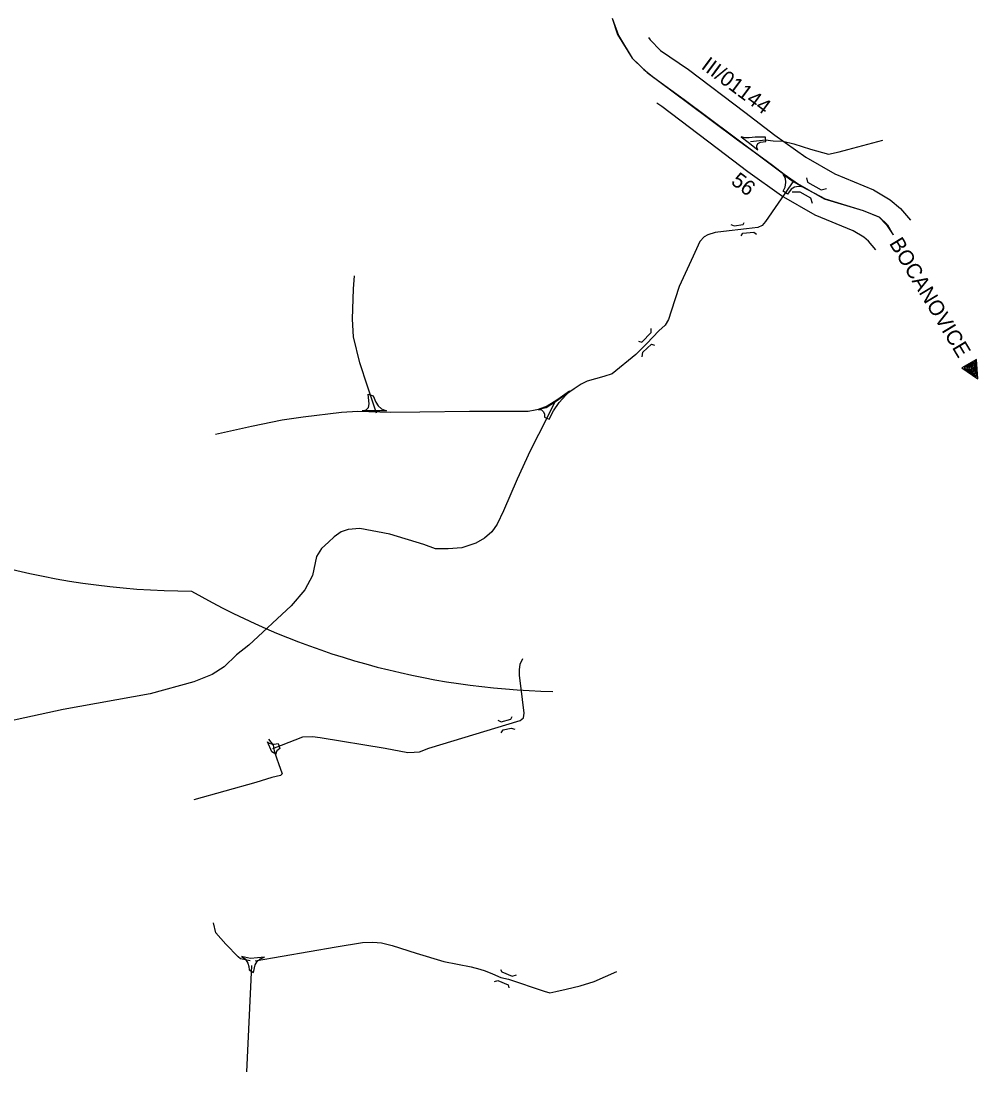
# Model space of a CAD drawing. Extents: x -444937 to -440733, y -1145714 to -1129798.
# Drawn here: x -441752 to -441120, y -1132642 to -1131949 of the extents above; entities that cross this region are included whole.
import ezdxf

# ---------------------------------------------------------------- set-up
doc = ezdxf.new("R2010")
doc.units = 0
for name, color, linetype in [('NIGP_sesuv_uz_P', 7, 'Continuous'), ('Vrstva 200', 7, 'Continuous'), ('Vrstva 7', 7, 'Continuous'), ('Vrstva 75', 7, 'Continuous'), ('Vrstva 8', 7, 'Continuous'), ('Vrstva 84', 7, 'Continuous')]:
    doc.layers.add(name, color=color, linetype=linetype)

msp = doc.modelspace()

# ---------------------------------------------------------------- linework, layer by layer
at = {"layer": 'NIGP_sesuv_uz_P'}
for centre, start, end in [((-441638.38, -1131824.9), 205.14125, 269.91178), ((-441390.5, -1131891.11), 240.17849, 268.81846)]:
    msp.add_arc(centre, 500, start, end, dxfattribs=at)
at = {"layer": 'Vrstva 200'}
for points in [[(-441337.66, -1131959.86), (-441336.59, -1131961.55), (-441329.85, -1131968.54), (-441311.37, -1131981.07), (-441274.26, -1132009.22), (-441254.45, -1132024.44), (-441233.88, -1132038.95), (-441214.75, -1132049.92), (-441189.45, -1132060.49), (-441178.41, -1132066.91), (-441171.49, -1132072.75), (-441164.95, -1132080.35)], [(-441187.71, -1132099.9), (-441192.66, -1132094.13), (-441195.76, -1132091.53), (-441202.83, -1132087.41), (-441227.75, -1132077.05), (-441250.02, -1132064.28), (-441272.24, -1132048.6), (-441292.47, -1132033.06), (-441328.87, -1132005.45), (-441332.27, -1132003.15)]]:
    msp.add_lwpolyline(points, dxfattribs=at)
at = {"layer": 'Vrstva 7'}
msp.add_lwpolyline([(-441361.7, -1131947.32), (-441358.1, -1131958.1), (-441348.47, -1131973.62), (-441338.59, -1131983.11), (-441311.96, -1132002.71), (-441279, -1132027.38), (-441268.13, -1132035.4), (-441250.5, -1132048.41), (-441236.51, -1132058.11), (-441221.25, -1132066.26), (-441196.14, -1132073.95), (-441185.83, -1132078.16), (-441180.75, -1132083.44), (-441176.33, -1132090.13)], dxfattribs=at)
for points in [[(-441120.42, -1132184.97), (-441121.41, -1132172.13), (-441131.09, -1132177.76)], [(-441121.35, -1132183.38), (-441122.11, -1132173.46), (-441129.59, -1132177.81)], [(-441122.27, -1132181.79), (-441122.81, -1132174.8), (-441128.08, -1132177.86)], [(-441123.2, -1132180.2), (-441123.51, -1132176.13), (-441126.58, -1132177.91)], [(-441124.12, -1132178.61), (-441124.21, -1132177.46), (-441125.08, -1132177.96)]]:
    msp.add_lwpolyline(points, close=True, dxfattribs=at)
at = {"layer": 'Vrstva 75'}
msp.add_lwpolyline([(-441361.7, -1131947.32), (-441357.55, -1131958.65), (-441348.47, -1131973.62), (-441340.75, -1131980.98), (-441334.18, -1131986.32), (-441314.19, -1132000.74), (-441282.12, -1132024.79), (-441271.55, -1132032.65), (-441255.99, -1132044.11), (-441242.54, -1132054.35), (-441221.84, -1132066.21), (-441196.14, -1132073.95), (-441185.42, -1132078.46), (-441180.16, -1132083.44), (-441176.33, -1132090.13)], dxfattribs=at)
at = {"layer": 'Vrstva 8'}
msp.add_line((-441602.74, -1132641.88), (-441599.44, -1132571.75), dxfattribs=at)
for points in [[(-441272.06, -1132028.95), (-441265.55, -1132033.96), (-441266.21, -1132032.52), (-441266.21, -1132031.3), (-441265.54, -1132029.95), (-441263.96, -1132028.89), (-441260.36, -1132028.6), (-441260.56, -1132025.71), (-441267.31, -1132025.71), (-441271.34, -1132026.2), (-441274.2, -1132026.16), (-441276.59, -1132025.47)], [(-441246.01, -1132063.22), (-441248.89, -1132061.23), (-441247.54, -1132058.64), (-441247.12, -1132055.49), (-441247.33, -1132052.76), (-441248.94, -1132050.16), (-441242.25, -1132054.88), (-441236.23, -1132058.33), (-441238.84, -1132058.09), (-441241.36, -1132058.6), (-441243.59, -1132059.94)], [(-441526.57, -1132206.08), (-441524.05, -1132205.39), (-441522.47, -1132203.85), (-441521.93, -1132201.46), (-441522.69, -1132195.04), (-441519.37, -1132196.09), (-441517.59, -1132200.46), (-441516.13, -1132202.81), (-441513.75, -1132204.77), (-441510.54, -1132206.01)], [(-441410.41, -1132205.23), (-441408.42, -1132205.5), (-441406.92, -1132206.71), (-441406.41, -1132208.21), (-441406.42, -1132210.18), (-441403.23, -1132211.61), (-441400.35, -1132206.02), (-441396.61, -1132200.54), (-441389.92, -1132193.17), (-441395.95, -1132197.42), (-441399.85, -1132200.07), (-441404.51, -1132202.95)], [(-441589.13, -1132424.28), (-441587.96, -1132425.19), (-441586.34, -1132425.67), (-441584.56, -1132425.76), (-441582.08, -1132425.39), (-441580.87, -1132428.67), (-441582.06, -1132429.45), (-441582.78, -1132430.14), (-441583.32, -1132431.3), (-441583.63, -1132432.49), (-441586.16, -1132430.77)], [(-441606.28, -1132565.86), (-441603.82, -1132567.4), (-441601.92, -1132570.05), (-441601.4, -1132572.3), (-441601.14, -1132574.44), (-441598.23, -1132576.37), (-441597.13, -1132571.26), (-441595.92, -1132568.95), (-441593.85, -1132567.22), (-441591.07, -1132566.09), (-441600.14, -1132567.02)]]:
    msp.add_lwpolyline(points, close=True, dxfattribs=at)
for points in [[(-441270.36, -1132028.42), (-441260.57, -1132027.47), (-441255.5, -1132028.04), (-441249.17, -1132028.32), (-441241.88, -1132030.17), (-441230.89, -1132033.55), (-441219.13, -1132036.9), (-441211.99, -1132035.28), (-441206.21, -1132033.89), (-441183.12, -1132027.68)], [(-441241.95, -1132054.31), (-441260.52, -1132081.21), (-441262.79, -1132083.85), (-441265.53, -1132085.27), (-441273.08, -1132086.13), (-441288.31, -1132087.92), (-441293.7, -1132088.49), (-441298.71, -1132090.09), (-441300.98, -1132091.42), (-441303.81, -1132094.44), (-441308.21, -1132104.11), (-441317.43, -1132124.17), (-441322.77, -1132140.31), (-441324.59, -1132145.92), (-441326.73, -1132149.55), (-441331.02, -1132153.34), (-441338.93, -1132161.75), (-441346.18, -1132169.01), (-441361.65, -1132181.66), (-441367.1, -1132183.33), (-441378.28, -1132186.52), (-441382.09, -1132188.54), (-441386.87, -1132191.57), (-441399.69, -1132200.6), (-441405.29, -1132204.07), (-441412.54, -1132205.65), (-441417.16, -1132206.51), (-441455.74, -1132206.49), (-441488.51, -1132206.94), (-441507.71, -1132207.24), (-441529.54, -1132206.58), (-441540.29, -1132207.21), (-441565.42, -1132210.34), (-441579.26, -1132212.11), (-441599.51, -1132216.47), (-441623.33, -1132221.72)], [(-441517.14, -1132207.55), (-441523.11, -1132189.91), (-441528.05, -1132174.41), (-441532.34, -1132157.26), (-441533, -1132145.72), (-441532.34, -1132125.6), (-441531.68, -1132117.06)], [(-441399.69, -1132200.6), (-441404.82, -1132210.89), (-441415.7, -1132232.33), (-441424.27, -1132251.13), (-441433.3, -1132272.03), (-441437.66, -1132280.79), (-441441.15, -1132285.85), (-441445.95, -1132289.94), (-441451.61, -1132293.26), (-441460.81, -1132296.31), (-441469.89, -1132297.02), (-441478.12, -1132296.95), (-441485.89, -1132294.15), (-441508.29, -1132287.43), (-441528.21, -1132283.57), (-441535.87, -1132284.21), (-441540.48, -1132285.85), (-441545.15, -1132289.13), (-441548.87, -1132292.6), (-441553.34, -1132296.85), (-441556.62, -1132302.11), (-441559.27, -1132314.5), (-441564.44, -1132324.04), (-441573.53, -1132334.68), (-441601.42, -1132360.57), (-441609.42, -1132366.88), (-441617.57, -1132374.87), (-441625.48, -1132379.81), (-441637.68, -1132384.66), (-441666.36, -1132392.57), (-441723.77, -1132403), (-441786.73, -1132416.52)], [(-441585.59, -1132428.61), (-441579.74, -1132426.38), (-441565.63, -1132420.93), (-441559.37, -1132420.66), (-441554.27, -1132421.3), (-441511.47, -1132428.43), (-441496.53, -1132431.19), (-441492.25, -1132431.13), (-441488.83, -1132430.89), (-441482.56, -1132428.43), (-441422.31, -1132410.29), (-441420.08, -1132408.44), (-441419.7, -1132405.29), (-441421.94, -1132387.27), (-441422.76, -1132380.55), (-441422.9, -1132376.85), (-441422.35, -1132373.15), (-441420.57, -1132369.32)], [(-441588.4, -1132422.57), (-441585.24, -1132426.43), (-441584.73, -1132430.16), (-441582.78, -1132435.46), (-441581.68, -1132438.6), (-441579.36, -1132445.39), (-441580.54, -1132446.4), (-441586.07, -1132447.69), (-441596.77, -1132450.97), (-441637.67, -1132462.44)], [(-441600.53, -1132568.72), (-441606.87, -1132567.3), (-441608.43, -1132565.97), (-441616.44, -1132557.55), (-441623.11, -1132550.12), (-441624.65, -1132543.61)], [(-441597.11, -1132568.71), (-441543.66, -1132559.33), (-441526.38, -1132556.59), (-441519.55, -1132556.26), (-441513.86, -1132556.76), (-441506.86, -1132558.44), (-441490.98, -1132563.47), (-441472.65, -1132569.1), (-441454.67, -1132572.64), (-441448.99, -1132574.08), (-441445.5, -1132575.21), (-441440.62, -1132577.21), (-441435.22, -1132579.56), (-441430.04, -1132580.75), (-441406.59, -1132588.7), (-441402.91, -1132589.76), (-441398.94, -1132588.77), (-441392.11, -1132587.32), (-441382.72, -1132585.03), (-441373.59, -1132582.24), (-441358.56, -1132575.72)]]:
    msp.add_lwpolyline(points, dxfattribs=at)
at = {"layer": 'Vrstva 84'}
for points in [[(-441233.45, -1132052.51), (-441232.83, -1132055.28), (-441223.75, -1132060.36), (-441220.43, -1132059.59)], [(-441242.88, -1132061.63), (-441238.03, -1132061.71), (-441230.79, -1132065.63), (-441229.71, -1132069.17)], [(-441283.44, -1132083.18), (-441281.29, -1132084.18), (-441275.35, -1132083.33), (-441274.72, -1132081.84)], [(-441276.66, -1132090.74), (-441275.58, -1132089.03), (-441268.27, -1132088.37), (-441266.49, -1132089.67)], [(-441344.32, -1132160.25), (-441342.04, -1132160.71), (-441336.06, -1132154.48), (-441335.99, -1132151.71)], [(-441341.95, -1132170.38), (-441341.45, -1132167.36), (-441335.73, -1132162.17), (-441333.84, -1132162.84)], [(-441437.01, -1132409.98), (-441434.81, -1132411), (-441428.49, -1132409.26), (-441427.67, -1132407.46)], [(-441434.94, -1132418.24), (-441433.56, -1132416.44), (-441428.27, -1132415.16), (-441426.01, -1132415.98)], [(-441435.36, -1132574.29), (-441434.49, -1132575.93), (-441427.77, -1132578.65), (-441424.79, -1132577.93)], [(-441439.21, -1132582.3), (-441437.11, -1132581.68), (-441430.38, -1132584.4), (-441429.77, -1132586.51)]]:
    msp.add_lwpolyline(points, dxfattribs=at)

# ---------------------------------------------------------------- texts
at = {"layer": 'Vrstva 7'}
for s, rotation, p in [('III/01144', 323.33947, (-441303.6, -1131980.04)), ('BOCANOVICE', 301.13022, (-441179.3, -1132095.6))]:
    msp.add_text(s, height=10, rotation=rotation, dxfattribs=at).set_placement(p)
at = {"layer": 'Vrstva 75'}
msp.add_text('56', height=10, rotation=322.46185, dxfattribs=at).set_placement((-441283.97, -1132055.98))

doc.saveas('drawing.dxf')
